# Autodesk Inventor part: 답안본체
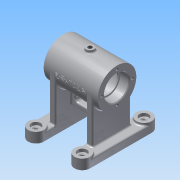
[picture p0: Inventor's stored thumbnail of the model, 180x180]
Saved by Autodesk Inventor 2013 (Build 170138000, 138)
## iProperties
Created: 2015-11
Part Number: 답안본체
Material: 알루미늄 6061
Document SubType Name: Modeling
Designer: ST3
Density: 2.71 g/cm^3
Mass: 357.973 g
Surface Area: 459.687 cm^2
Volume: 132.093 cm^3
Author: ST3
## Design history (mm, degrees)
sketch "스케치1"
  geometry: L1 (-35, 0)-(35, 0); L2 (-35, 16)-(-35, 25); L3 (-35, 25)-(35, 25); L4 (35, 25)-(35, 16); L5 (35, 16)-(23, 16); L6 (23, 16)-(23, 14); L7 (23, 14)-(21, 14); L8 (21, 14)-(21, 21); L9 (21, 21)-(-21, 21); L10 (-21, 21)-(-21, 14); L11 (-21, 14)-(-23, 14); L12 (-23, 14)-(-23, 16); L13 (-23, 16)-(-35, 16); 1 further point
  constraints: 26 end point, 10 parallel, 2 perpendicular, 1 horizontal
  dimensions: "d0" = 0 distance from line of point (0, 0) L1; "d1" = 70 distance of L1.start L1.end; "d2" = 35 distance of point (0, 0) L1.start (= 0.5 x d1); "d3" = 70 distance between parallel lines of L4 L2; "d4" = 42 diameter of L9 L1; "d5" = 50 diameter of L3 L1; "d6" = 28 diameter of L7 L1; "d7" = 28 diameter of L11 L1; "d8" = 32 diameter of L13 L1; "d9" = 32 diameter of L5 L1; "d10" = 12 distance of L4.end L5.end; "d11" = 12 distance of L12.end L2.start; "d12" = 42 distance between parallel lines of L8 L10; "d13" = 2 distance of L10.end L11.end; "d14" = 0 distance from line of L2 L1.start
revolve "회전1" sketch "스케치1" stored, may be unused: angle "d15" = 90 deg
node "작업 평면1"
sketch "스케치3"
  geometry: L1 (40, 40)-(40, -40); L2 (20, 40)-(20, -40); A1 r 10 centre (30, 40) between (40, 40) and (20, 40); A2 r 10 centre (30, -40) between (20, -40) and (40, -40); 1 further point
  constraints: 4 end point, 4 point on circle, 3 tangent, 2 centre point, 1 vertical
  dimensions: "d28" = 80 distance of A2.centre A1.centre; "d32" = 20 diameter of A1; "d33" = 20 diameter of A2; "d34" = 40 vertical distance of point (0, 0) A1.centre (= 0.5 x d28); "d44" = 40 distance from line of L1 point (0, 0); "d45" = 20 distance from line of L2 point (0, 0)
extrude "돌출2" join sketch "스케치3" distance "d35" = 10; taper "d36" = 0 deg
sketch "스케치4"
  geometry: L1 (10, 0)-(10, -80) reference; L2 (2, -15)-(10, -15); L3 (10, -15)-(10, -65); L4 (10, -65)-(2, -65); L5 (2, -65)-(2, -15); 1 further point
  constraints: 8 end point, 2 parallel, 1 horizontal, 1 perpendicular, 1 point on line
  dimensions: "d37" = 8 distance between parallel lines of L3 L5; "d39" = 50 distance between parallel lines of L4 L2; "d40" = 25 distance from line of point (30, -40) L2 (= 0.5 x d39)
extrude "돌출3" join sketch "스케치4" stored distance "d41" = 10; taper "d42" = 0 deg
sketch "스케치5"
  geometry: L1 (35, -25)-(-35, -25) reference; L2 (20, -45)-(-20, -45); L3 (-20, -58)-(-20, 0) reference; L4 (20, -58)-(20, 0) reference; 1 further point
  constraints: 2 end point
feature "리브1" sketch "스케치5" dims "d48" = 1, "d49" = 8, "d50" = 0, "d51" = 0, "d52" = 1, "d53" = 1
sketch "스케치6"
  geometry: L1 (40, 0)-(0, 0) reference; L2 (0, 43.322)-(-20, 43.322) reference; L3 (40, 43.322)-(60, 43.322) reference; L4 (31.5, 6.822)-(8.5, 6.822); L5 (31.5, 13.822)-(8.5, 13.822); A1 r 3.5 centre (31.5, 10.322) between (31.5, 6.822) and (31.5, 13.822); A2 r 3.5 centre (8.5, 10.322) between (8.5, 13.822) and (8.5, 6.822); 2 further points
  constraints: 4 end point, 4 point on circle, 3 tangent, 2 centre point, 1 midpoint, 1 parallel
  dimensions: "d54" = 23 distance of A2.centre A1.centre; "d56" = 11.5 horizontal distance of point (20, 0) A1.centre (= 0.5 x d54); "d57" = 7 diameter of A1; "d58" = 7 diameter of A2; "d59" = 33 distance from line of A2.centre L2; "d60" = 33 distance from line of A1.centre L3
extrude "돌출4" cut sketch "스케치6" stored distance "d61" = 10; taper "d62" = 0 deg
fillet "모깎기1" dims "d63" = 2
fillet "모깎기2" dims "d64" = 2
fillet "모깎기3" dims "d65" = 2
fillet "모깎기4" dims "d66" = 2
chamfer "모따기1" distance "d67" = 1; stored, may be unused: second distance "d68" = 2, angle "d69" = 45 deg
fillet "모깎기5" dims "d70" = 3
fillet "모깎기6" dims "d71" = 0.3
sketch "스케치7" dims "d72" = 40
  geometry: C1 r 25 at (0, 0) reference; C2 r 17 at (0, 0) reference; 2 further points
  constraints: 1 coincident, 1 horizontal alignment, 2 other
  dimensions: "d74" = 0 vertical distance of point (-20, 0) C1.centre
hole "구멍1" sketch "스케치7" at (-20, 0) diameter "d75" = 3.242; stored, may be unused: countersink angle "d79" = 90 deg, drill point angle "d81" = 118 deg; dims "d76" = 8, "d77" = 4, "d78" = 2, "d80" = 10
node "작업 평면3"
sketch "스케치8"
  geometry: C1 r 5 at (0, 0); 1 further point
  constraints: 1 centre point, 1 coincident
  dimensions: "d86" = 10 diameter of C1
extrude "돌출5" join sketch "스케치8" stored distance "d88" = 10; taper "d89" = 0 deg
sketch "스케치9"
  geometry: C1 r 5 at (0, 0) reference
hole "구멍2" sketch "스케치9" at (0, 0) diameter "d93" = 5.188; stored, may be unused: countersink angle "d97" = 90 deg, drill point angle "d99" = 118 deg; dims "d94" = 8, "d95" = 4, "d96" = 2, "d98" = 10
sketch "스케치10"
  geometry: L1 (70, -80)-(70, 0) reference; L2 (50, 0)-(50, -80) reference; C1 r 10 at (0, 0); C2 r 10 at (0, -80); A1 r 10 centre (0, 0) between (10, 0) and (-10, 0) reference; A2 r 10 centre (0, -80) between (-10, -80) and (10, -80) reference; A3 r 10 centre (60, 0) between (70, 0) and (50, 0) reference; A4 r 10 centre (60, -80) between (50, -80) and (70, -80) reference; 3 further points
  constraints: 4 coincident, 2 centre point, 2 concentric, 2 horizontal alignment, 4 other
extrude "돌출6" join sketch "스케치10" distance "d103" = 3; taper "d104" = 0 deg
sketch "스케치11"
  geometry: L1 (70, 0)-(70, 80) reference; L2 (50, 80)-(50, 0) reference; L3 (10, 80)-(10, 0) reference; L4 (-10, 0)-(-10, 80) reference; C1 r 10 at (0, 0) reference; A1 r 10 centre (60, 80) between (70, 80) and (50, 80) reference; A2 r 10 centre (60, 0) between (50, 0) and (70, 0) reference; A3 r 10 centre (0, 80) between (10, 80) and (-10, 80) reference; A4 r 10 centre (0, 0) between (-10, 0) and (10, 0) reference; 1 further point
hole "구멍3" sketch "스케치11" at (0, 0), (60, 0), (60, 80), (0, 80) diameter "d105" = 6; stored, may be unused: countersink angle "d109" = 82 deg, drill point angle "d111" = 0 deg; dims "d106" = 8, "d107" = 12, "d108" = 4, "d110" = 13
fillet "모깎기7" dims "d112" = 2
fillet "모깎기8" dims "d113" = 2
fillet "모깎기9" dims "d114" = 2
node "작업 평면4"
sketch "스케치15"
  geometry: L1 (-25.873, 3.002)-(25.873, 3.002); L2 (25.873, 3.002)-(25.873, -3.002); L3 (25.873, -3.002)-(-25.873, -3.002); L4 (-25.873, -3.002)-(-25.873, 3.002); L5 (-25.873, 0)-(25.873, 0); L6 (0, -3.002)-(0, 3.002); L7 (-35, 25)-(35, 25) reference; L8 (-35, -25)-(-35, 25) reference; 1 further point
  constraints: 4 end point, 4 midpoint, 2 other
  dimensions: "d127" = 25 distance between parallel lines of L7 L5; "d128" = 35 distance between parallel lines of L8 L6
feature "엠보싱1" sketch "스케치15" dims "d39" = 50, "d40" = 25 (= 0.5 x d39), "d44" = 40, "d78" = 2, "d85" = 28, "d114" = 2, "d129" = 0.5, "d130" = 0, "d144" = 12
sketch "스케치16"
  geometry: L1 (0, 0)-(26.734, -46.305); L2 (2.536, -45)-(-2.536, -45) reference; L3 (0, 0)-(0, -45); L4 (12.5, -21.651)-(30.959, -10.993); C1 r 1.621 at (20, 0) reference; C2 r 1.621 at (0, -20) reference; C3 r 1.621 at (-20, 0) reference; C4 r 1.621 at (0, 20) reference; C5 r 17 at (0, 0) reference; 4 further points
  constraints: 6 end point, 1 midpoint, 1 point on line, 3 other
  dimensions: "d141" = 30 deg angle of L3 L1; "d142" = 90 deg angle of L1 L4
  node "투영된 루프4"
node "작업 평면7"
node "작업 평면10"
  node "작업 평면9"
sketch "스케치17"
  geometry: C1 r 6 at (0, 0); 1 further point
  constraints: 1 centre point, 1 coincident
  dimensions: "d144" = 12 diameter of C1
extrude "돌출7" join sketch "스케치17" stored distance "d146" = 3; taper "d147" = 0 deg
sketch "스케치18"
  geometry: C1 r 6 at (0, 0) reference
hole "구멍5" sketch "스케치18" at (0, 0) diameter "d148" = 5.188; stored, may be unused: countersink angle "d152" = 82 deg, drill point angle "d154" = 0 deg; dims "d149" = 8, "d150" = 12, "d151" = 4, "d153" = 13
fillet "모깎기11" dims "d155" = 2
fillet "모깎기12" dims "d156" = 0.3
chamfer "모따기2" distance "d157" = 1; stored, may be unused: second distance "d158" = 2, angle "d159" = 45 deg
node "솔리드1"
mirror "대칭2"
mirror "대칭3"
pattern_circular "원형 패턴1" dims angle "d83" = 360 deg
mirror "대칭4"
node "투영된 루프1"
node "투영된 루프2"
node "투영된 루프3"
other parameters: "d16" = -68, "d126" = -44.5, "d143" = 3
